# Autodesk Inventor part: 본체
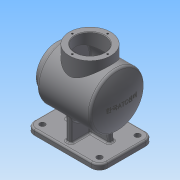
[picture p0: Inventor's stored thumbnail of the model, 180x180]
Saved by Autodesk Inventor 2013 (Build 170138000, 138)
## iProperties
Created: 2016-09
Part Number: 본체
Material: 일반
Document SubType Name: Modeling
Designer: Administrator
Density: 1 g/cm^3
Author: Administrator
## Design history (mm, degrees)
sketch "스케치1"
  geometry: L1 (-67.5, 50)-(67.5, 50); L2 (67.5, 50)-(67.5, -50); L3 (67.5, -50)-(-67.5, -50); L4 (-67.5, -50)-(-67.5, 50); C1 r 5 at (-52.5, -35); C2 r 5 at (52.5, -35); C3 r 5 at (52.5, 35); C4 r 5 at (-52.5, 35); 5 further points
  constraints: 8 end point, 4 centre point, 4 horizontal alignment, 4 midpoint, 4 vertical alignment, 3 equal radius, 2 parallel, 1 horizontal, 1 perpendicular
  dimensions: "d0" = 135 distance of L1.start L1.end; "d2" = 100 distance of L1.end L2.end; "d3" = 10 diameter of C4; "d4" = 15 distance from line of L4 C4.centre; "d5" = 15 distance from line of L1 C4.centre; "d6" = 15 distance from line of L3 C1.centre; "d7" = 15 distance from line of L2 C2.centre
extrude "돌출1" new body sketch "스케치1" distance "d8" = 10; taper "d9" = 0 deg
sketch "스케치2"
  geometry: L1 (-61, 82)-(61, 82); L2 (-67.5, 0)-(67.5, 0) reference; L3 (-61, 82)-(-61, 120); L4 (-61, 120)-(-49, 120); L5 (-49, 120)-(-49, 132); L6 (-49, 132)-(49.562, 132); A1 r 115 centre (-54, 82) between (61, 82) and (49.562, 132); 3 further points
  constraints: 10 end point, 2 parallel, 2 perpendicular, 2 point on circle, 1 centre point, 1 coincident, 1 horizontal, 1 midpoint, 1 point on line, 1 vertical alignment
  dimensions: "d10" = 122 distance of L1.end L1.start; "d13" = 82 vertical distance of L2.start L1.start; "d14" = 7 distance of L1.start point (-54, 82); "d15" = 76 diameter of L4 L1; "d16" = 100 diameter of L6 L1; "d17" = 12 distance of L3.end L4.end
revolve "회전1" sketch "스케치2" stored, may be unused: angle "d18" = 90 deg
node "작업 평면1"
sketch "스케치3"
  geometry: C1 r 38 at (0, 0); 1 further point
  constraints: 1 centre point, 1 coincident
  dimensions: "d20" = 76 diameter of C1
extrude "돌출2" join sketch "스케치3" distance "d21" = 65; taper "d22" = 0 deg
sketch "스케치4"
  geometry: L1 (-67.5, 0)-(67.5, 0) reference; L2 (67.5, 10)-(-67.5, 10) reference; L3 (-40, 10)-(-36.181, 53.649); L4 (-36.181, 53.649)-(36.181, 53.649); L5 (36.181, 53.649)-(40, 10); 1 further point
  constraints: 6 end point, 2 point on line, 1 parallel
  dimensions: "d23" = 40 horizontal distance of L3.start point (0, 0); "d24" = 40 horizontal distance of point (0, 0) L5.end; "d25" = 95 deg angle of L2 L3; "d26" = 95 deg angle of L2 L5; "d27" = 43.64903 distance between parallel lines of L2 L4
extrude "돌출3" join sketch "스케치4" stored distance "d28" = 10; taper "d29" = 0 deg
sketch "스케치5"
  geometry: L1 (50, 10)-(-50, 10) reference; L2 (-50, 0)-(50, 0) reference; L3 (-40, 10)-(-40, 57.422); L4 (-40, 57.422)-(40, 57.422); L5 (40, 57.422)-(40, 10); 1 further point
  constraints: 6 end point, 2 perpendicular, 2 point on line, 1 parallel
  dimensions: "d30" = 40 horizontal distance of L3.start point (0, 0); "d31" = 40 horizontal distance of point (0, 0) L5.end; "d32" = 47.42184 distance between parallel lines of L1 L4
extrude "돌출4" join sketch "스케치5" stored distance "d33" = 10; taper "d34" = 0 deg
node "작업 평면2"
node "작업 평면3"
sketch "스케치7"
  geometry: 2 further points
  constraints: 1 vertical alignment, 1 other
  dimensions: "d37" = 82 distance of point (0, 0) point (0, 82)
feature "엠보싱1" sketch "스케치7" dims "d0" = 135, "d2" = 100, "d3" = 10, "d4" = 15, "d5" = 15, "d6" = 15, "d7" = 15, "d38" = 0.5, "d39" = 0
sketch "스케치8"
  geometry: L1 (-61, 82)-(61, 82); L2 (-67.5, 0)-(67.5, 0) reference; L3 (-61, 82)-(-61, 109); L4 (-61, 109)-(-46, 109); L5 (-46, 109)-(-46, 129); L6 (-46, 129)-(47.661, 129); L7 (-49, 132)-(49.562, 132) reference; A1 r 115 centre (-54, 82) between (49.562, 32) and (49.562, 132) reference; A2 r 112 centre (-54, 82) between (58, 82) and (47.661, 129); 3 further points
  constraints: 10 end point, 4 perpendicular, 2 point on circle, 2 point on line, 1 centre point, 1 coincident, 1 horizontal, 1 midpoint, 1 vertical alignment
  dimensions: "d40" = 122 distance of L1.start L1.end; "d42" = 82 distance between parallel lines of L2 L1; "d45" = 54 diameter of L4 L1; "d46" = 15 distance of L3.end L4.end; "d47" = 7 distance of L1.start point (-54, 82); "d49" = 224 diameter of A2; "d50" = 94 diameter of L6 L1
revolve "회전2" sketch "스케치8" stored, may be unused: angle "d51" = 90 deg
hole "구멍1" diameter "d54" = 54; stored, may be unused: countersink angle "d58" = 90 deg, drill point angle "d60" = 0 deg; dims "d52" = 10, "d53" = 10, "d55" = 6, "d56" = 4, "d57" = 2, "d59" = 40
sketch "스케치9"
  geometry: 2 further points
  constraints: 1 horizontal alignment
  dimensions: "d61" = 114.5 distance of point (82, 0) point (-32.5, 0)
hole "구멍2" sketch "스케치9" at (-32.5, 0) diameter "d62" = 3.242; stored, may be unused: countersink angle "d66" = 90 deg, drill point angle "d68" = 118 deg; dims "d63" = 8, "d64" = 4, "d65" = 2, "d67" = 10
sketch "스케치10"
  geometry: L1 (61, 38)-(61, -38) reference; 2 further points
  constraints: 1 vertical alignment
  dimensions: "d72" = 32.5 distance of point (0, 0) point (0, 32.5)
hole "구멍3" sketch "스케치10" at (0, 32.5) diameter "d73" = 3.242; stored, may be unused: countersink angle "d77" = 90 deg, drill point angle "d79" = 118 deg; dims "d74" = 8, "d75" = 4, "d76" = 2, "d78" = 10
fillet "모깎기1" dims "d83" = 15
fillet "모깎기2" dims "d84" = 5
fillet "모깎기3" dims "d85" = 5
fillet "모깎기4" dims "d86" = 2
fillet "모깎기5" dims "d87" = 2
fillet "모깎기6" dims "d88" = 3
fillet "모깎기7" dims "d89" = 3
fillet "모깎기8" dims "d90" = 3
fillet "모깎기9" dims "d91" = 3
fillet "모깎기10" dims "d92" = 3
chamfer "모따기1" distance "d93" = 1; stored, may be unused: second distance "d94" = 2, angle "d95" = 45 deg
chamfer "모따기2" distance "d96" = 1; stored, may be unused: second distance "d97" = 2, angle "d98" = 45 deg
node "솔리드1"
pattern_circular "원형 패턴1" dims angle "d70" = 360 deg
pattern_circular "원형 패턴2" dims angle "d81" = 360 deg
other parameters: "d19" = 82, "d36" = -48
